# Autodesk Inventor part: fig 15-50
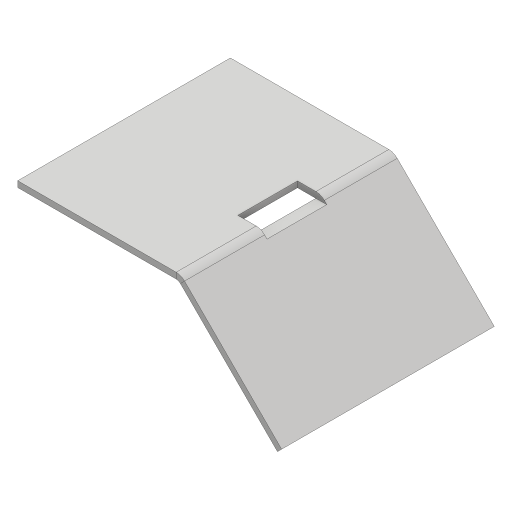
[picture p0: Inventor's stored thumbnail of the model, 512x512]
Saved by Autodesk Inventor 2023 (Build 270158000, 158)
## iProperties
Created: 2015-07
Part Number: fig 15-50
Material: Generic
Document SubType Name: Sheet Metal
Designer: Sandeep
Density: 1 g/cm^3
Sheet Metal Rule: Default_mm
Appearance: Default
Author: Sandeep
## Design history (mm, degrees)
node "Face1"
  sketch "Sketch1"
    geometry: L1 (-9.283, 8.313)-(4.503, 8.313); L2 (4.503, 8.313)-(4.503, -9.63); L3 (4.503, -9.63)-(-9.283, -9.63); L4 (-9.283, -9.63)-(-9.283, 8.313); 1 further point
    constraints: 8 end point, 2 parallel, 1 horizontal, 1 perpendicular
node "Flange1"
sketch "Sketch3"
  geometry: L1 (2.535, 2.162)-(6.789, 2.162); L2 (6.789, 2.162)-(6.789, -2.878); L3 (6.789, -2.878)-(2.535, -2.878); L4 (2.535, -2.878)-(2.535, 2.162); 1 further point
  constraints: 8 end point, 2 parallel, 1 horizontal, 1 perpendicular
cut "Cut1" sketch "Sketch3" dims "d11" = 0.5 (= Thickness), "d12" = 0
body "Solid1"
face "Plate1" dims "d13" = 0.5 (= Thickness)
sketch "Sketch2"
  geometry: L1 (0, -12)-(17.943, -12); L2 (17.943, -12)-(17.943, 0); 1 other entity
  constraints: 4 end point, 4 other
face "Plate2" dims "d1" = 0.5 (= BendReliefWidth), "d2" = 0.25 (= BendReliefDepth), "d3" = 1 (= MinimumRemnant), "d4" = 0.5 (= BendRadius), "d5" = 12, "d6" = 45 deg, "d7" = 0.5 (= BendRadius), "d8" = 2 (= CornerReliefSize), "d9" = 0.5 (= GapSize), "d10" = 0.5 (= JacobiRadiusSize), "d13" = 0.5 (= Thickness), "SeamGap" = 0.01
bend "Bend1" dims "d1" = 0.5 (= BendReliefWidth), "d2" = 0.25 (= BendReliefDepth), "d3" = 1 (= MinimumRemnant), "d4" = 0.5 (= BendRadius), "d5" = 12, "d6" = 45 deg, "d7" = 0.5 (= BendRadius), "d13" = 0.5 (= Thickness), "SeamGap" = 0.01
feature "Corner1" dims "d5" = 12, "d6" = 45 deg, "d8" = 2 (= CornerReliefSize), "d9" = 0.5 (= GapSize), "d10" = 0.5 (= JacobiRadiusSize)
other parameters: "Thickness" = 0.5, "BendRadius" = 0.5 (= Thickness), "BendReliefWidth" = 0.5 (= Thickness), "BendReliefDepth" = 0.25 (= 0.5 x Thickness), "CornerReliefSize" = 2 (= 4 x Thickness), "MinimumRemnant" = 1 (= 2 x Thickness), "TransitionRadius" = 0.5 (= BendRadius), "JacobiRadiusSize" = 0.5 (= BendRadius), "GapSize" = 0.5 (= Thickness), "d0" = 0.5 (= BendRadius)
